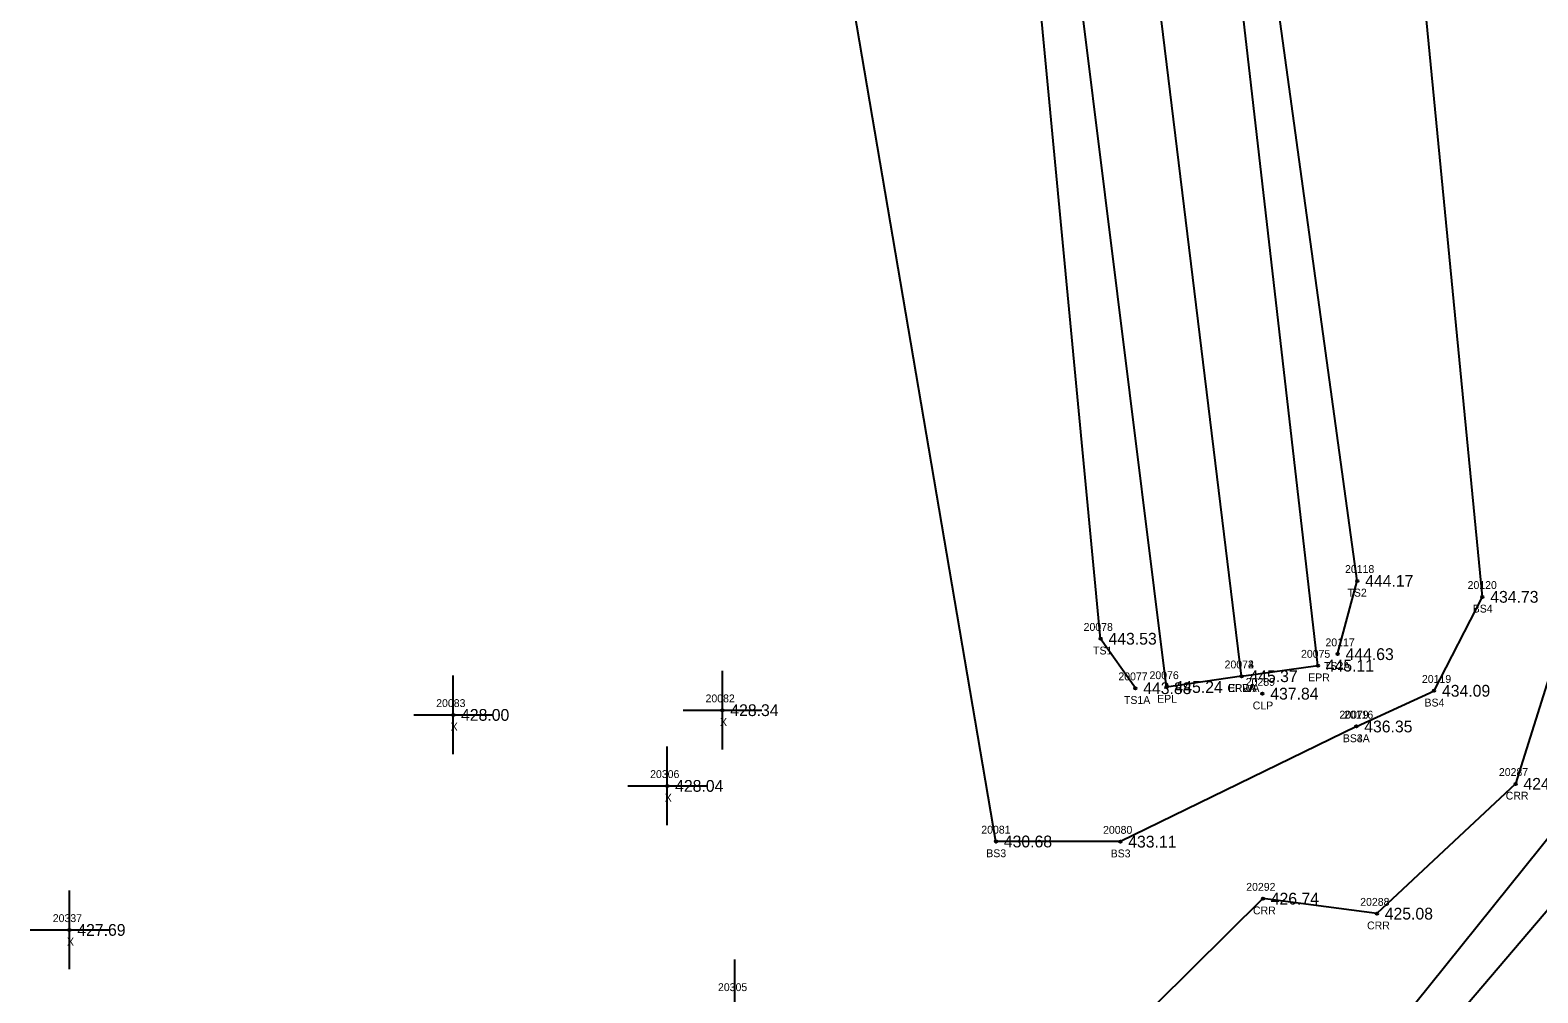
# Model space of a CAD drawing. Extents: x 1858461 to 1858936, y 1147060 to 1148183.
# Drawn here: x 1858524.9 to 1858716.7, y 1147619.9 to 1147742.4 of the extents above; entities that cross this region are included whole.
import ezdxf

# ---------------------------------------------------------------- set-up
doc = ezdxf.new("R2010")
doc.units = 0
for name, color, linetype in [('RD_DTM_BkLn1', 7, 'Continuous'), ('RD_DTM_BkLn2', 7, 'Continuous'), ('RD_DTM_BkLn_txCode', 7, 'Continuous'), ('RD_EX_H2O', 7, 'Continuous'), ('RD_EX_H2O_txCode', 7, 'Continuous'), ('RD_EX_Misc', 7, 'Continuous'), ('RD_EX_Misc_txCode', 7, 'Continuous'), ('RD_EX_Road', 7, 'Continuous'), ('RD_EX_Road_txCode', 7, 'Continuous'), ('RD_EX_TX_H2O_ELEV', 7, 'Continuous'), ('RD_EX_TX_Misc_ELEV', 7, 'Continuous'), ('RD_EX_TX_Road_ELEV', 7, 'Continuous'), ('RD_HC_Survey_ELEV', 7, 'Continuous'), ('RD_HC_Survey_txCode', 7, 'Continuous'), ('RD_SMD_Locator', 7, 'Continuous')]:
    doc.layers.add(name, color=color, linetype=linetype)

msp = doc.modelspace()

# ---------------------------------------------------------------- linework, layer by layer
at = {"layer": 'RD_DTM_BkLn1'}
msp.add_lwpolyline([(1858679.02, 1147660.19), (1858666.85, 1147759.91), (1858654.47, 1147859.47), (1858641.87, 1147959.15), (1858630.02, 1148056.08), (1858617.26, 1148157.44)], dxfattribs=at)
at = {"layer": 'RD_DTM_BkLn2'}
for points in [[(1858693.62, 1147653.8), (1858703.51, 1147658.34), (1858709.65, 1147670.29), (1858700.15, 1147768.19), (1858693.67, 1147865.34), (1858675.79, 1147959.77), (1858663.27, 1148067), (1858650.31, 1148162.46)], [(1858691.24, 1147663), (1858693.74, 1147672.32), (1858681.4, 1147761.99), (1858668.07, 1147861.46), (1858660.68, 1147960.55), (1858649.11, 1148060.84), (1858635.41, 1148160.22)], [(1858693.62, 1147653.8), (1858663.6, 1147639.15), (1858647.78, 1147639.17), (1858628.12, 1147754.45), (1858616.79, 1147851.29), (1858607.32, 1147958.26), (1858596.73, 1148053.14), (1858583.42, 1148154.64)], [(1858665.51, 1147658.67), (1858661.09, 1147664.96), (1858652.2, 1147758.21), (1858640.05, 1147857.23), (1858625.95, 1147957.13), (1858612.72, 1148055.44), (1858600.29, 1148155.52)]]:
    msp.add_lwpolyline(points, dxfattribs=at)
at = {"layer": 'RD_EX_H2O'}
for points in [[(1858883.69, 1148147.48), (1858852.78, 1148112.64), (1858836.04, 1148037.73), (1858833.26, 1147975.2), (1858828.33, 1147910.84), (1858842, 1147848.22), (1858847.52, 1147794.04), (1858841.16, 1147786.48), (1858816.23, 1147769.28), (1858759.58, 1147742.8), (1858751.47, 1147732.35), (1858731.2, 1147689.66), (1858724.77, 1147677.64), (1858718.76, 1147662.14), (1858713.87, 1147646.5), (1858696.23, 1147629.99), (1858681.73, 1147631.9), (1858663.61, 1147613.98)], [(1858909.91, 1148115.72), (1858902.77, 1148116.75), (1858903.07, 1148125.04), (1858896.61, 1148132.76), (1858873.78, 1148129.33), (1858855.27, 1148111.83), (1858840.09, 1148036.93), (1858846.14, 1147982.36), (1858846.9, 1147967.54), (1858840.1, 1147928.32), (1858835.96, 1147922.3), (1858846.22, 1147851.69), (1858849.56, 1147834.44), (1858863.29, 1147789.22), (1858867.71, 1147772.35), (1858865.71, 1147761.59), (1858842.61, 1147761.06), (1858828.27, 1147754.21), (1858821.34, 1147763.04), (1858764.94, 1147737.1), (1858734.3, 1147688.97), (1858719.03, 1147640.86), (1858697.04, 1147613.49)], [(1858867.04, 1148108.26), (1858855.22, 1148032.48), (1858854.94, 1147976.71), (1858844.75, 1147924.02), (1858838.88, 1147914.94), (1858851.14, 1147854.11), (1858872.36, 1147792.48), (1858884.3, 1147779.68), (1858885.3, 1147773.97), (1858872.32, 1147746.91), (1858824.97, 1147749.39), (1858805.62, 1147746.07), (1858768.36, 1147727.81), (1858744.99, 1147687.5), (1858739.82, 1147673.18), (1858724.58, 1147638.24), (1858698.73, 1147607.87)]]:
    msp.add_lwpolyline(points, dxfattribs=at)
at = {"layer": 'RD_EX_Misc'}
for p, q in [((1858578.74, 1147650.27), (1858578.74, 1147660.27)), ((1858612.99, 1147650.87), (1858612.99, 1147660.87)), ((1858573.74, 1147655.27), (1858583.74, 1147655.27)), ((1858607.99, 1147655.87), (1858617.99, 1147655.87)), ((1858605.97, 1147641.24), (1858605.97, 1147651.24)), ((1858600.97, 1147646.24), (1858610.97, 1147646.24)), ((1858529.93, 1147622.92), (1858529.93, 1147632.92)), ((1858524.93, 1147627.92), (1858534.93, 1147627.92)), ((1858614.58, 1147614.14), (1858614.58, 1147624.14))]:
    msp.add_line(p, q, dxfattribs=at)
at = {"layer": 'RD_EX_Road'}
for points in [[(1858679.02, 1147660.19), (1858688.73, 1147661.54), (1858677.21, 1147761.6), (1858664.75, 1147860.38), (1858652.33, 1147959.9), (1858640.18, 1148058.71), (1858627.63, 1148158.94)], [(1858679.02, 1147660.19), (1858669.49, 1147658.82), (1858657, 1147758.92), (1858643.96, 1147857.84), (1858631.87, 1147958), (1858619.69, 1148055.49), (1858606.59, 1148156.75)]]:
    msp.add_lwpolyline(points, dxfattribs=at)
at = {"layer": 'RD_SMD_Locator'}
for centre in [(1858693.74, 1147672.32), (1858709.65, 1147670.29), (1858661.09, 1147664.96), (1858691.24, 1147663), (1858688.73, 1147661.54), (1858679.02, 1147660.19), (1858679.02, 1147660.19), (1858679.02, 1147660.19), (1858665.51, 1147658.67), (1858669.49, 1147658.82), (1858681.67, 1147657.97), (1858703.51, 1147658.34), (1858578.74, 1147655.27), (1858612.99, 1147655.87), (1858693.62, 1147653.8), (1858693.62, 1147653.8), (1858605.97, 1147646.24), (1858713.87, 1147646.5), (1858647.78, 1147639.17), (1858663.6, 1147639.15), (1858681.73, 1147631.9), (1858696.23, 1147629.99), (1858529.93, 1147627.92)]:
    msp.add_circle(centre, 0.15, dxfattribs=at)

# ---------------------------------------------------------------- texts
at = {"layer": 'RD_DTM_BkLn_txCode'}
for s, p in [('20118', (1858692.18, 1147673.32)), ('TS2', (1858692.49, 1147670.32)), ('20120', (1858707.77, 1147671.29)), ('BS4', (1858708.42, 1147668.29)), ('20078', (1858658.93, 1147665.96)), ('20117', (1858689.69, 1147664)), ('TS1', (1858660.13, 1147662.96)), ('TS2A', (1858689.51, 1147661)), ('20077', (1858663.35, 1147659.67)), ('20119', (1858701.96, 1147659.34)), ('TS1A', (1858664.06, 1147656.67)), ('BS4', (1858702.29, 1147656.34)), ('20079', (1858691.46, 1147654.8)), ('20116', (1858692.05, 1147654.8)), ('BS3A', (1858691.9, 1147651.8)), ('BS4A', (1858691.9, 1147651.8)), ('20081', (1858645.91, 1147640.17)), ('20080', (1858661.4, 1147640.15)), ('BS3', (1858646.55, 1147637.17)), ('BS3', (1858662.37, 1147637.15))]:
    msp.add_text(s, height=1, dxfattribs=at).set_placement(p)
at = {"layer": 'RD_EX_H2O_txCode'}
for s, p in [('20287', (1858711.75, 1147647.5)), ('CRR', (1858712.62, 1147644.5)), ('20292', (1858679.61, 1147632.9)), ('CRR', (1858680.47, 1147629.9)), ('20288', (1858694.11, 1147630.99)), ('CRR', (1858694.98, 1147627.99))]:
    msp.add_text(s, height=1, dxfattribs=at).set_placement(p)
at = {"layer": 'RD_EX_Misc_txCode'}
for s, p in [('20083', (1858576.58, 1147656.27)), ('20082', (1858610.84, 1147656.87)), ('X', (1858578.42, 1147653.27)), ('X', (1858612.68, 1147653.87)), ('20306', (1858603.79, 1147647.24)), ('X', (1858605.65, 1147644.24)), ('20337', (1858527.81, 1147628.92)), ('X', (1858529.62, 1147625.92)), ('20305', (1858612.42, 1147620.14))]:
    msp.add_text(s, height=1, dxfattribs=at).set_placement(p)
at = {"layer": 'RD_EX_Road_txCode'}
for s, p in [('20075', (1858686.58, 1147662.54)), ('20072', (1858676.86, 1147661.19)), ('20073', (1858676.86, 1147661.19)), ('20076', (1858667.31, 1147659.82)), ('EPRA', (1858677.3, 1147658.19)), ('EPLA', (1858677.32, 1147658.19)), ('EPR', (1858687.5, 1147659.54)), ('EPL', (1858668.28, 1147656.82))]:
    msp.add_text(s, height=1, dxfattribs=at).set_placement(p)
at = {"layer": 'RD_EX_TX_H2O_ELEV'}
for s, p in [('424.07', (1858714.87, 1147645.75)), ('426.74', (1858682.73, 1147631.15)), ('425.08', (1858697.23, 1147629.24))]:
    msp.add_text(s, height=1.5, dxfattribs=at).set_placement(p)
at = {"layer": 'RD_EX_TX_Misc_ELEV'}
for s, p in [('444.17', (1858694.74, 1147671.57)), ('434.73', (1858710.65, 1147669.54)), ('443.53', (1858662.09, 1147664.21)), ('444.63', (1858692.24, 1147662.25)), ('443.88', (1858666.51, 1147657.92)), ('434.09', (1858704.51, 1147657.59)), ('428.00', (1858579.74, 1147654.52)), ('428.34', (1858613.99, 1147655.12)), ('436.35', (1858694.62, 1147653.05)), ('436.35', (1858694.62, 1147653.05)), ('428.04', (1858606.97, 1147645.49)), ('430.68', (1858648.78, 1147638.42)), ('433.11', (1858664.6, 1147638.4)), ('427.69', (1858530.93, 1147627.17))]:
    msp.add_text(s, height=1.5, dxfattribs=at).set_placement(p)
at = {"layer": 'RD_EX_TX_Road_ELEV'}
for s, p in [('445.37', (1858680.02, 1147659.44)), ('445.37', (1858680.02, 1147659.44)), ('445.11', (1858689.73, 1147660.79)), ('445.24', (1858670.49, 1147658.07))]:
    msp.add_text(s, height=1.5, dxfattribs=at).set_placement(p)
at = {"layer": 'RD_HC_Survey_ELEV'}
for s, p in [('445.37', (1858680.02, 1147659.44)), ('437.84', (1858682.67, 1147657.22))]:
    msp.add_text(s, height=1.5, dxfattribs=at).set_placement(p)
at = {"layer": 'RD_HC_Survey_txCode'}
for s, p in [('20074', (1858676.86, 1147661.19)), ('CRWA', (1858677.21, 1147658.19)), ('20289', (1858679.55, 1147658.97)), ('CLP', (1858680.44, 1147655.97))]:
    msp.add_text(s, height=1, dxfattribs=at).set_placement(p)

doc.saveas('drawing.dxf')
